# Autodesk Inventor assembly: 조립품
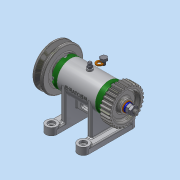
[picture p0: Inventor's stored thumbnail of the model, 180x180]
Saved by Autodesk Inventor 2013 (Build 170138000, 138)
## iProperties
Created: 2015-11
Part Number: 조립품
Document SubType Name: Assembly
Designer: ST4
Author: ST4
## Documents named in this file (16)
- C:\Users\ST4\Desktop\451109V1017\조립품.iam
- C:\Users\ST4\Desktop\451109V1017\본체.ipt
- C:\Users\ST4\Desktop\451109V1017\V벨트풀리.ipt
- C:\Users\ST4\Desktop\451109V1017\너트 M 8.ipt
- C:\Users\ST4\Desktop\451109V1017\니플 M 6 x 0.75.ipt
- C:\Users\ST4\Desktop\451109V1017\베어링 15 x 32 x 9.ipt
- C:\Users\ST4\Desktop\451109V1017\볼트 M 6 x 8.ipt
- C:\Users\ST4\Desktop\451109V1017\볼트 M4 x 12.ipt
- C:\Users\ST4\Desktop\451109V1017\스퍼기어.ipt
- C:\Users\ST4\Desktop\451109V1017\스프링와셔 8.ipt
- C:\Users\ST4\Desktop\451109V1017\오일 실 15 25 7.ipt
- C:\Users\ST4\Desktop\451109V1017\와셔 6x11.5.ipt
- C:\Users\ST4\Desktop\451109V1017\와셔 8x17.ipt
- C:\Users\ST4\Desktop\451109V1017\축.ipt
- C:\Users\ST4\Desktop\451109V1017\커버.ipt
- C:\Users\ST4\Desktop\451109V1017\키 3 x 3 x 12.ipt
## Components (11 placed, 3 different names)
1. V벨트풀리:1
2. KS B 2023 6002 - 15 x 32 x 9:1
3. ISO 4762 M4 x 12:1
4. ISO 4762 M4 x 12:2
5. ISO 4762 M4 x 12:3
6. ISO 4762 M4 x 12:4
7. ISO 4762 M4 x 12:5
8. ISO 4762 M4 x 12:6
9. ISO 4762 M4 x 12:7
10. ISO 4762 M4 x 12:8
11. KS B 2023 6002 - 15 x 32 x 9:2
